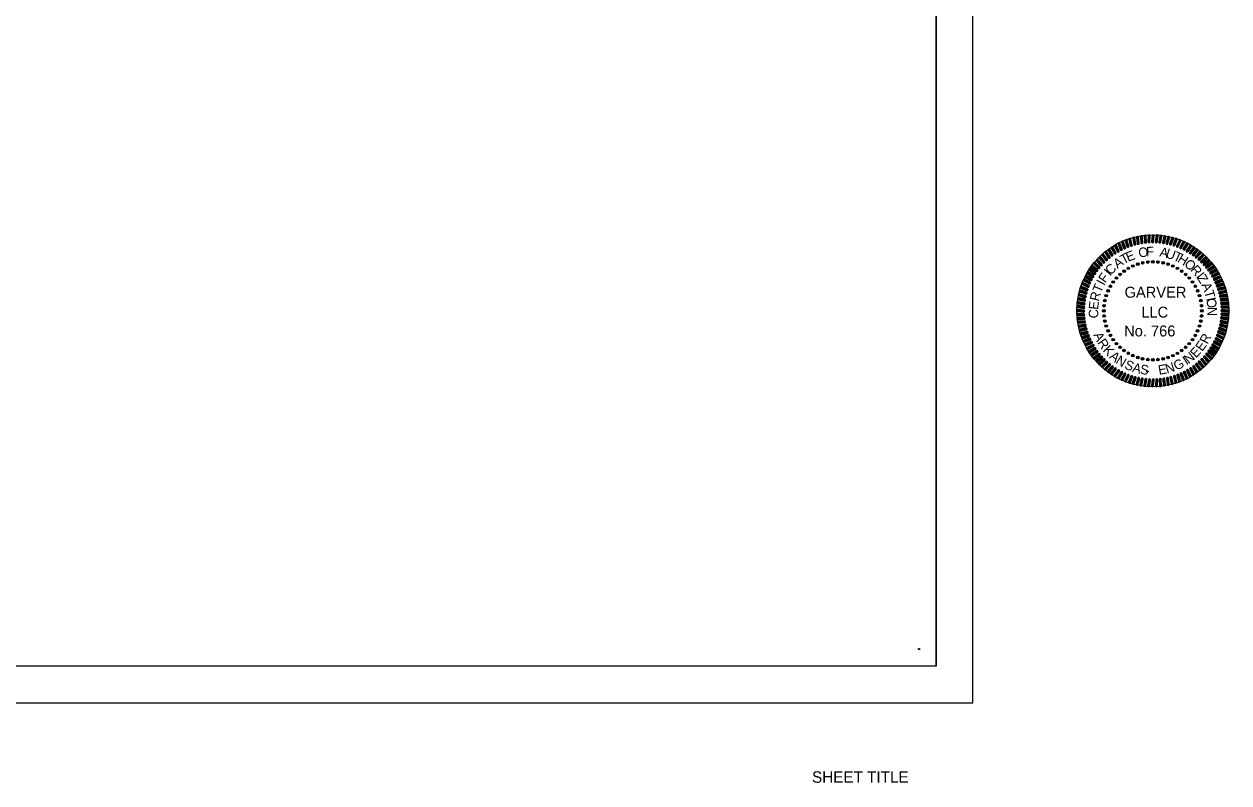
# Model space of a CAD drawing. Extents: x 0 to 19, y -0.6 to 11.3.
# Drawn here: x 9.51 to 19.02, y -0.63 to 5.36 of the extents above; entities that cross this region are included whole.
import ezdxf

# ---------------------------------------------------------------- set-up
doc = ezdxf.new("R2010")
doc.units = 0
for name, color, linetype in [('G-ANNO-STMP', 7, 'Continuous'), ('G-ANNO-TEXT', 7, 'Continuous'), ('G-Border-Paper', 7, 'Continuous'), ('G-Border-Sheet', 7, 'Continuous'), ('G-No Plot-Anchor', 7, 'Continuous'), ('G-No Plot-Border-1', 7, 'Continuous'), ('G-No Plot-Border-2', 7, 'Continuous'), ('G-No Plot-Stamp-1', 7, 'Continuous'), ('G-No Plot-Stamp-2', 7, 'Continuous')]:
    doc.layers.add(name, color=color, linetype=linetype)

# ---------------------------------------------------------------- blocks, each defined once
blk = doc.blocks.new('SEALDO')
at = {"layer": 'G-ANNO-TEXT'}
for radius in [0.0396, 0.0305, 0.0213, 0.0122, 0.00305]:
    blk.add_circle((1.403, -0.456), radius, dxfattribs=at)
blk = doc.blocks.new('SEALRI')
at = {"layer": 'G-ANNO-TEXT'}
for p, q in [((-0.023, 2.258), (-0.038, 2.081)), ((-0.008, 2.281), (-0.028, 2.056)), ((0.004, 2.286), (-0.016, 2.049)), ((0.016, 2.285), (-0.004, 2.048)), ((0.028, 2.278), (0.008, 2.052)), ((0.023, 2.076), (0.038, 2.253))]:
    blk.add_line(p, q, dxfattribs=at)
for centre, start, end in [((0.008, 2.256), 355, 175), ((-0.008, 2.078), 175, 355)]:
    blk.add_arc(centre, 0.0305, start, end, dxfattribs=at)

msp = doc.modelspace()

# ---------------------------------------------------------------- linework, layer by layer
at = {"layer": 'G-Border-Paper'}
msp.add_lwpolyline([(17, 11), (0, 11), (0, 0), (17, 0)], close=True, dxfattribs=at)
at = {"layer": 'G-Border-Sheet'}
for q in [(16.7116, 10.7116), (0.758, 0.2884)]:
    msp.add_line((16.7116, 0.2884), q, dxfattribs=at)
at = {"layer": 'G-No Plot-Anchor'}
msp.add_circle((16.5766, 0.4234), 0.005, dxfattribs=at)
at = {"layer": 'G-No Plot-Border-1'}
msp.add_lwpolyline([(0.758, 0.2884), (0.758, 10.7116), (13.7281, 10.7116), (13.7281, 10.2161), (15.4366, 10.2161), (15.4366, 8.7411), (16.7116, 8.7411), (16.7116, 0.2884)], close=True, dxfattribs=at)
at = {"layer": 'G-No Plot-Border-2'}
msp.add_lwpolyline([(0.758, 0.2884), (0.758, 10.7116), (12.3781, 10.7116), (12.3781, 9.2366), (13.7281, 9.2366), (13.7281, 10.2161), (14.7206, 10.2161), (16.7116, 10.2161), (16.7116, 0.2884)], close=True, dxfattribs=at)
at = {"layer": 'G-No Plot-Stamp-1'}
msp.add_circle((18.4222, 3.0925), 0.6, dxfattribs=at)
at = {"layer": 'G-No Plot-Stamp-2'}
msp.add_circle((18.4222, 3.0925), 0.6, dxfattribs=at)

# ---------------------------------------------------------------- block references
at = {"layer": 'G-ANNO-STMP'}
for name, xscale, yscale, rotation in [('SEALRI', 0.2624620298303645, 0.2624620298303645, 30.00000000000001), ('SEALRI', 0.2624620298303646, 0.26246202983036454, 26.99999999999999), ('SEALRI', 0.26246202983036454, 0.26246202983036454, 23.99999999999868), ('SEALRI', 0.26246202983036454, 0.26246202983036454, 20.999999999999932), ('SEALRI', 0.2624620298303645, 0.26246202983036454, 18), ('SEALRI', 0.2624620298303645, 0.2624620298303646, 15.000000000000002), ('SEALRI', 0.2624620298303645, 0.2624620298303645, 12.000000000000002), ('SEALRI', 0.2624620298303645, 0.2624620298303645, 9), ('SEALRI', 0.2624620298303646, 0.26246202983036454, 6), ('SEALRI', 0.2624620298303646, 0.2624620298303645, 3.0000000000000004), ('SEALRI', 0.26246202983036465, 0.2624620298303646, -2.9999999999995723), ('SEALRI', 0.2624620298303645, 0.2624620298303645, -5.9999999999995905), ('SEALRI', 0.2624620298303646, 0.26246202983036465, -8.999999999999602), ('SEALRI', 0.2624620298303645, 0.26246202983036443, -11.999999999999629), ('SEALRI', 0.2624620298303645, 0.2624620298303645, -14.999999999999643), ('SEALRI', 0.26246202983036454, 0.2624620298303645, -17.99999999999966), ('SEALRI', 0.2624620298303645, 0.26246202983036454, -20.999999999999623), ('SEALRI', 0.2624620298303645, 0.26246202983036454, -23.999999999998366), ('SEALRI', 0.26246202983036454, 0.26246202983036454, -26.999999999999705), ('SEALRI', 0.26246202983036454, 0.2624620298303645, -29.99999999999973), ('SEALRI', 0.26246202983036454, 0.2624620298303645, 44.999999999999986), ('SEALRI', 0.26246202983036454, 0.2624620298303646, 41.999999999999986), ('SEALRI', 0.26246202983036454, 0.26246202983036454, 38.999999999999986), ('SEALRI', 0.2624620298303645, 0.2624620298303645, 36), ('SEALRI', 0.2624620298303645, 0.26246202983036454, 33), ('SEALRI', 0.26246202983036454, 0.2624620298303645, -32.999999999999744), ('SEALRI', 0.2624620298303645, 0.2624620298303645, -35.999999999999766), ('SEALRI', 0.26246202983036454, 0.2624620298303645, -38.999999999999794), ('SEALRI', 0.26246202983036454, 0.2624620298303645, -41.99999999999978), ('SEALRI', 0.26246202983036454, 0.2624620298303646, -44.999999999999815), ('SEALRI', 0.26246202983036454, 0.2624620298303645, 56.99999999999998), ('SEALRI', 0.2624620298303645, 0.2624620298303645, 54), ('SEALRI', 0.26246202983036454, 0.26246202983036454, 50.99999999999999), ('SEALRI', 0.2624620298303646, 0.26246202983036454, 47.99999999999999), ('SEALDO', 0.26246202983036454, 0.26246202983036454, 138), ('SEALDO', 0.2624620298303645, 0.26246202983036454, 131.99999999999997), ('SEALDO', 0.2624620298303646, 0.26246202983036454, 125.99999999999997), ('SEALDO', 0.2624620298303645, 0.26246202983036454, 119.99999999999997), ('SEALDO', 0.2624620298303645, 0.26246202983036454, 113.99999999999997), ('SEALDO', 0.26246202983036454, 0.2624620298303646, 107.99999999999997), ('SEALDO', 0.26246202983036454, 0.26246202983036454, 101.99999999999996), ('SEALDO', 0.2624620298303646, 0.2624620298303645, 95.99999999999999), ('SEALDO', 0.26246202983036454, 0.26246202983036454, 90), ('SEALDO', 0.2624620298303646, 0.26246202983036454, 83.99999999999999), ('SEALDO', 0.2624620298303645, 0.26246202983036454, 77.99999999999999), ('SEALRI', 0.26246202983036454, 0.2624620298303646, -47.99999999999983), ('SEALRI', 0.2624620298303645, 0.26246202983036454, -50.999999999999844), ('SEALRI', 0.2624620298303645, 0.26246202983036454, -53.99999999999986), ('SEALRI', 0.2624620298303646, 0.26246202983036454, -56.999999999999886), ('SEALRI', 0.26246202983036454, 0.2624620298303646, 65.99999999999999), ('SEALRI', 0.26246202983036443, 0.2624620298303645, 63), ('SEALRI', 0.2624620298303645, 0.2624620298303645, 59.999999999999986), ('SEALDO', 0.2624620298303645, 0.26246202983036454, 162.00000000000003), ('SEALDO', 0.26246202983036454, 0.2624620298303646, 156.00000000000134), ('SEALDO', 0.26246202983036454, 0.2624620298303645, 150), ('SEALDO', 0.2624620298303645, 0.26246202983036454, 144), ('SEALDO', 0.2624620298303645, 0.26246202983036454, 72), ('SEALDO', 0.26246202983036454, 0.2624620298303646, 66.00000000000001), ('SEALDO', 0.26246202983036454, 0.2624620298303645, 60.00000000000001), ('SEALDO', 0.2624620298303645, 0.2624620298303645, 54), ('SEALRI', 0.2624620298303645, 0.26246202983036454, -59.99999999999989), ('SEALRI', 0.2624620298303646, 0.26246202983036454, -62.99999999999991), ('SEALRI', 0.26246202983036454, 0.2624620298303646, -65.99999999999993), ('SEALRI', 0.2624620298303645, 0.26246202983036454, 75.00000000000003), ('SEALRI', 0.2624620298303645, 0.26246202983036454, 72), ('SEALRI', 0.26246202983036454, 0.2624620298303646, 68.99999999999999), ('SEALDO', 0.2624620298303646, 0.2624620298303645, 174.00000000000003), ('SEALDO', 0.26246202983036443, 0.2624620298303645, 168.00000000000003), ('SEALDO', 0.26246202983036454, 0.2624620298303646, 48.00000000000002), ('SEALDO', 0.2624620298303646, 0.26246202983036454, 42.000000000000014), ('SEALRI', 0.26246202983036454, 0.26246202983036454, -68.99999999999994), ('SEALRI', 0.26246202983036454, 0.26246202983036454, -71.99999999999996), ('SEALRI', 0.26246202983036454, 0.2624620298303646, -74.99999999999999), ('SEALRI', 0.2624620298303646, 0.26246202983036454, 84.00000000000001), ('SEALRI', 0.2624620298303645, 0.2624620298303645, 81), ('SEALRI', 0.2624620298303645, 0.2624620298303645, 78.00000000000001), ('SEALDO', 0.2624620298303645, 0.26246202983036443, -167.99999999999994), ('SEALDO', 0.26246202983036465, 0.26246202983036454, -173.99999999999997), ('SEALDO', 0.26246202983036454, 0.26246202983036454, -179.99999999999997), ('SEALDO', 0.2624620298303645, 0.2624620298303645, 36), ('SEALDO', 0.26246202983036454, 0.2624620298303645, 29.999999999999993), ('SEALDO', 0.26246202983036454, 0.26246202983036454, 23.99999999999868), ('SEALRI', 0.2624620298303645, 0.2624620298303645, -78), ('SEALRI', 0.2624620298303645, 0.2624620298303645, -81.00000000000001), ('SEALRI', 0.2624620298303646, 0.2624620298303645, -84.00000000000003), ('SEALRI', 0.26246202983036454, 0.26246202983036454, 90.00000000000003), ('SEALRI', 0.26246202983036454, 0.26246202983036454, 87.00000000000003), ('SEALRI', 0.2624620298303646, 0.2624620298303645, 93), ('SEALRI', 0.2624620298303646, 0.26246202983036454, 96.00000000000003), ('SEALDO', 0.2624620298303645, 0.26246202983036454, -161.99999999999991), ('SEALDO', 0.2624620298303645, 0.26246202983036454, -156.00000000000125), ('SEALDO', 0.2624620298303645, 0.2624620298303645, 12.000000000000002), ('SEALDO', 0.2624620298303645, 0.26246202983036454, 18), ('SEALRI', 0.26246202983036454, 0.2624620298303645, -96.0000000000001), ('SEALRI', 0.26246202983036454, 0.26246202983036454, -87.00000000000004), ('SEALRI', 0.2624620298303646, 0.26246202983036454, -93.00000000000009), ('SEALRI', 0.26246202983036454, 0.26246202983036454, -90.00000000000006), ('SEALRI', 0.26246202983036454, 0.26246202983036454, 99.00000000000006), ('SEALRI', 0.2624620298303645, 0.2624620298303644, 102.00000000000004), ('SEALRI', 0.26246202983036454, 0.2624620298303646, 105.00000000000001), ('SEALDO', 0.26246202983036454, 0.26246202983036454, -149.99999999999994), ('SEALDO', 0.2624620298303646, 0.26246202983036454, -143.99999999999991), ('SEALDO', 0.26246202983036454, 0.2624620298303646, -137.9999999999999), ('SEALDO', 0.2624620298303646, 0.26246202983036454, 6), ('SEALRI', 0.26246202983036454, 0.2624620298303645, -105.00000000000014), ('SEALRI', 0.2624620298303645, 0.2624620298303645, -102.00000000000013), ('SEALRI', 0.26246202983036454, 0.2624620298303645, -99.00000000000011), ('SEALRI', 0.26246202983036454, 0.26246202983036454, 108.00000000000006), ('SEALRI', 0.2624620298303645, 0.2624620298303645, 111.00000000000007), ('SEALRI', 0.26246202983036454, 0.26246202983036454, 114.00000000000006), ('SEALRI', 0.26246202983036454, 0.26246202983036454, 117.00000000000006), ('SEALDO', 0.26246202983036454, 0.26246202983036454, -131.99999999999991), ('SEALDO', 0.26246202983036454, 0.2624620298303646, -125.9999999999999), ('SEALDO', 0.2624620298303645, 0.26246202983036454, -18.000000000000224), ('SEALDO', 0.2624620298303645, 0.26246202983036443, -12.000000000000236), ('SEALDO', 0.26246202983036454, 0.2624620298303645, -6.000000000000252), ('SEALRI', 0.26246202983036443, 0.2624620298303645, -117.00000000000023), ('SEALRI', 0.26246202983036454, 0.2624620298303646, -114.0000000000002), ('SEALRI', 0.26246202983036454, 0.26246202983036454, -111.00000000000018), ('SEALRI', 0.26246202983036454, 0.2624620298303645, -108.00000000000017), ('SEALRI', 0.2624620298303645, 0.2624620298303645, 120.00000000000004), ('SEALRI', 0.2624620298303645, 0.2624620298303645, 123.00000000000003), ('SEALRI', 0.26246202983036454, 0.26246202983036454, 126.00000000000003), ('SEALRI', 0.26246202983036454, 0.26246202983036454, 129.00000000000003), ('SEALDO', 0.2624620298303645, 0.26246202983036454, -119.99999999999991), ('SEALDO', 0.26246202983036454, 0.26246202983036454, -113.99999999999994), ('SEALDO', 0.26246202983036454, 0.26246202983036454, -107.99999999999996), ('SEALDO', 0.2624620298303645, 0.26246202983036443, -101.99999999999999), ('SEALDO', 0.2624620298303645, 0.2624620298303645, -42.00000000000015), ('SEALDO', 0.2624620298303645, 0.2624620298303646, -36.00000000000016), ('SEALDO', 0.2624620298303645, 0.26246202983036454, -30.00000000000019), ('SEALDO', 0.26246202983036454, 0.2624620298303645, -23.999999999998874), ('SEALRI', 0.2624620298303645, 0.26246202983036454, -129.00000000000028), ('SEALRI', 0.26246202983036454, 0.2624620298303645, -126.00000000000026), ('SEALRI', 0.2624620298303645, 0.26246202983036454, -123.00000000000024), ('SEALRI', 0.26246202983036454, 0.2624620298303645, -120.00000000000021), ('SEALRI', 0.26246202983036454, 0.2624620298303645, 132), ('SEALRI', 0.2624620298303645, 0.26246202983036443, 135), ('SEALRI', 0.26246202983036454, 0.26246202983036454, 138), ('SEALRI', 0.2624620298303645, 0.26246202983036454, 140.99999999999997), ('SEALRI', 0.2624620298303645, 0.26246202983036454, 144), ('SEALDO', 0.2624620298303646, 0.26246202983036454, -96), ('SEALDO', 0.26246202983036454, 0.26246202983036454, -90.00000000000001), ('SEALDO', 0.2624620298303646, 0.2624620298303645, -84.00000000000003), ('SEALDO', 0.26246202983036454, 0.26246202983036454, -78.00000000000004), ('SEALDO', 0.26246202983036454, 0.2624620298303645, -72.00000000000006), ('SEALDO', 0.2624620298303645, 0.26246202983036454, -66.00000000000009), ('SEALDO', 0.26246202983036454, 0.26246202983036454, -60.0000000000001), ('SEALDO', 0.26246202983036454, 0.26246202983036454, -54.000000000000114), ('SEALDO', 0.26246202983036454, 0.26246202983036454, -48.00000000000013), ('SEALRI', 0.2624620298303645, 0.26246202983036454, -144.00000000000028), ('SEALRI', 0.26246202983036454, 0.2624620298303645, -141.0000000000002), ('SEALRI', 0.26246202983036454, 0.2624620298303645, -138.00000000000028), ('SEALRI', 0.2624620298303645, 0.2624620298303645, -135.00000000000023), ('SEALRI', 0.2624620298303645, 0.26246202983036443, -132.00000000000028), ('SEALRI', 0.2624620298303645, 0.26246202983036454, 146.99999999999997), ('SEALRI', 0.2624620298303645, 0.26246202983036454, 149.99999999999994), ('SEALRI', 0.2624620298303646, 0.26246202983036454, 152.99999999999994), ('SEALRI', 0.2624620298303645, 0.2624620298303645, 156.00000000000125), ('SEALRI', 0.2624620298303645, 0.26246202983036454, 159), ('SEALRI', 0.2624620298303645, 0.2624620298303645, 161.99999999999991), ('SEALRI', 0.2624620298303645, 0.26246202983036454, 164.99999999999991), ('SEALRI', 0.2624620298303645, 0.26246202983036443, 167.99999999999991), ('SEALRI', 0.2624620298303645, 0.2624620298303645, -168.0000000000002), ('SEALRI', 0.2624620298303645, 0.2624620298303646, -165.0000000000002), ('SEALRI', 0.2624620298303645, 0.26246202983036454, -162.00000000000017), ('SEALRI', 0.26246202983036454, 0.26246202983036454, -159.00000000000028), ('SEALRI', 0.2624620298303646, 0.2624620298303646, -156.00000000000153), ('SEALRI', 0.2624620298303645, 0.2624620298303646, -153.00000000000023), ('SEALRI', 0.2624620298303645, 0.26246202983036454, -150.00000000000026), ('SEALRI', 0.26246202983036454, 0.2624620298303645, -147.00000000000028), ('SEALRI', 0.26246202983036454, 0.2624620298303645, 170.9999999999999), ('SEALRI', 0.26246202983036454, 0.2624620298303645, 173.9999999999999), ('SEALRI', 0.2624620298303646, 0.2624620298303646, 176.9999999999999), ('SEALRI', 0.26246202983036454, 0.26246202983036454, 179.99999999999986), ('SEALRI', 0.2624620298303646, 0.26246202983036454, -177.00000000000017), ('SEALRI', 0.2624620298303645, 0.2624620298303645, -174.00000000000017), ('SEALRI', 0.26246202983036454, 0.2624620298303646, -171.00000000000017)]:
    msp.add_blockref(name, (18.4223, 3.0925), dxfattribs=dict(at, xscale=xscale, yscale=yscale, rotation=rotation))
at = {"layer": 'G-ANNO-STMP', "xscale": 0.26246202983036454, "yscale": 0.26246202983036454}
for name in ['SEALRI', 'SEALDO']:
    msp.add_blockref(name, (18.4223, 3.0925), dxfattribs=at)

# ---------------------------------------------------------------- texts
at = {"layer": 'G-ANNO-STMP'}
for s, rotation, p in [('T', 28.2771, (18.1905, 3.4573)), ('E', 21.61044, (18.2267, 3.4785)), ('O', 8.2771, (18.3136, 3.5123)), ('F', 1.61044, (18.3705, 3.522)), ('A', 348.2771, (18.4707, 3.5227)), ('U', 341.27715, (18.5176, 3.5152)), ('T', 334.94377, (18.5765, 3.4962)), ('H', 328.2771, (18.6103, 3.4828)), ('I', 49.74076, (18.0858, 3.3622)), ('C', 44.38813, (18.0896, 3.3699)), ('A', 34.94377, (18.1428, 3.4228)), ('O', 319.7874, (18.6645, 3.452)), ('R', 311.99331, (18.7137, 3.4128)), ('I', 61.61044, (18.0378, 3.2871)), ('F', 54.94377, (18.0468, 3.3073)), ('I', 307.00814, (18.7595, 3.3613)), ('Z', 301.61044, (18.7683, 3.3523)), ('R', 74.94377, (17.9951, 3.1629)), ('T', 67.43139, (18.0126, 3.2289)), ('A', 292.97516, (18.8037, 3.2978)), ('T', 286.3085, (18.8272, 3.2435)), ('E', 83.89849, (17.9897, 3.0987)), ('I', 281.61044, (18.8422, 3.1908)), ('O', 276.48226, (18.8451, 3.1881)), ('C', 91.88416, (17.993, 3.0347)), ('N', 268.2771, (18.8545, 3.1248)), ('A', 296.57465, (17.9514, 2.9025)), ('R', 304.61826, (17.981, 2.8408)), ('E', 54.73091, (18.8126, 2.7672)), ('R', 63.09594, (18.8543, 2.8247)), ('K', 313.3805, (18.0231, 2.778)), ('A', 321.25836, (18.0738, 2.7232)), ('N', 38.98211, (18.705, 2.6701)), ('E', 46.68075, (18.7629, 2.7159)), ('N', 329.10994, (18.1231, 2.6817)), ('S', 337.62936, (18.1923, 2.6396)), ('A', 345.40726, (18.2555, 2.613)), ('S', 352.80457, (18.3191, 2.5952)), ('E', 10.06947, (18.4713, 2.5871)), ('N', 17.86862, (18.5341, 2.5965)), ('G', 26.41319, (18.608, 2.6194)), ('I', 32.97899, (18.6876, 2.6612)), ('-', 0.83848, (18.3644, 2.5854))]:
    msp.add_text(s, height=0.075, rotation=rotation, dxfattribs=at).set_placement(p)
for s, p in [('GARVER', (18.1993, 3.1961)), ('LLC', (18.3314, 3.039)), ('No. 766', (18.1956, 2.8903))]:
    msp.add_text(s, height=0.0864, dxfattribs=at).set_placement(p)
at = {"layer": 'G-ANNO-TEXT'}
msp.add_text('SHEET TITLE', height=0.09, dxfattribs=at).set_placement((15.7319, -0.6318))

doc.saveas('drawing.dxf')
